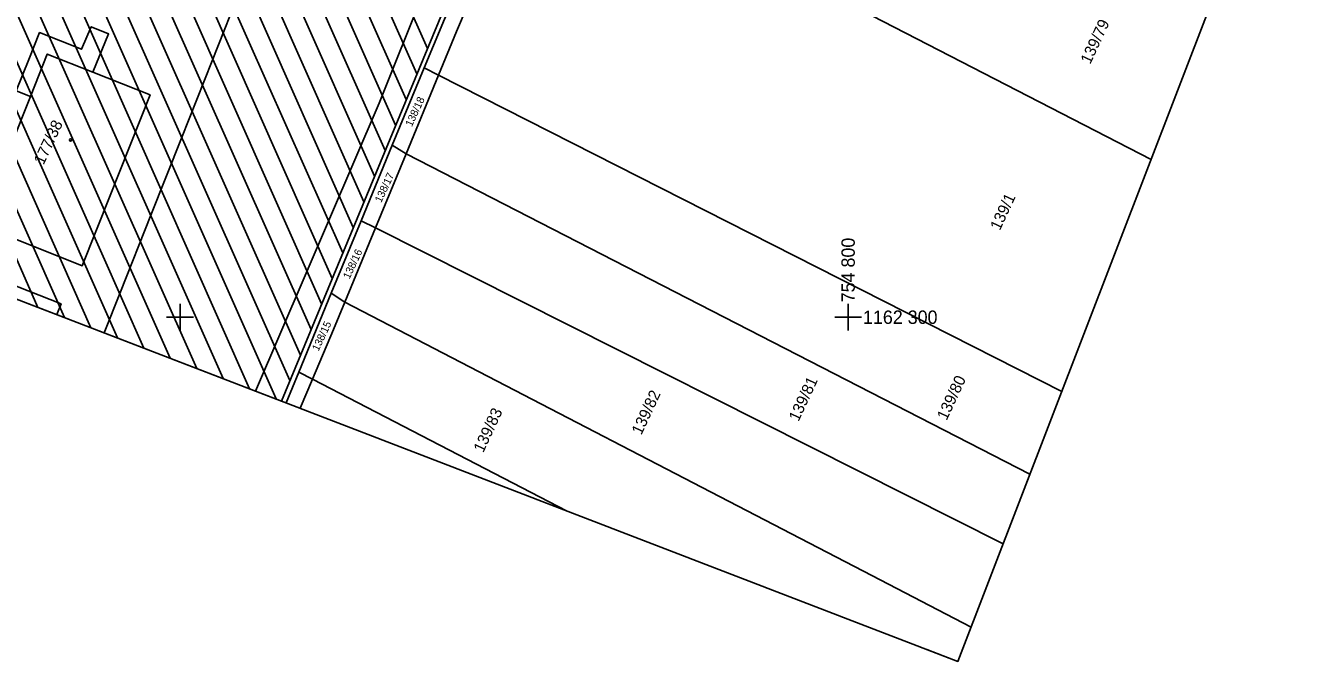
# Model space of a CAD drawing. Extents: x -755061 to -754557, y -1162352 to -1161657.
# Drawn here: x -754923.1 to -754731.6, y -1162351.5 to -1162256.4 of the extents above; entities that cross this region are included whole.
import ezdxf

# ---------------------------------------------------------------- set-up
doc = ezdxf.new("R2010")
doc.units = 0
for name, color, linetype in [('ADJ_Formát', 7, 'Continuous'), ('ADJ_Síť', 7, 'Continuous'), ('DTA_správa_investora', 7, 'Continuous'), ('KN_Katastrální hranice', 7, 'Continuous'), ('KN_Vrstva 55', 7, 'Continuous'), ('KN_Vrstva 56', 7, 'Continuous'), ('KN_Vrstva 57', 7, 'Continuous'), ('KN_Vrstva 59', 7, 'Continuous'), ('Vrstva 53', 7, 'Continuous')]:
    doc.layers.add(name, color=color, linetype=linetype)

msp = doc.modelspace()

# ---------------------------------------------------------------- linework, layer by layer
at = {"layer": 'ADJ_Formát'}
msp.add_line((-754783.57, -1162351.52), (-754788.23, -1162349.72), dxfattribs=at)
msp.add_lwpolyline([(-754909.9, -1161852.87), (-754632.71, -1161959.54), (-754783.57, -1162351.52), (-755060.75, -1162244.84)], close=True, dxfattribs=at)
at = {"layer": 'ADJ_Síť'}
for points in [[(-754900, -1162298), (-754900, -1162300), (-754900, -1162302)], [(-754900, -1162298), (-754900, -1162300), (-754900, -1162302)], [(-754800, -1162298), (-754800, -1162300), (-754800, -1162302)], [(-754800, -1162298), (-754800, -1162300), (-754800, -1162302)], [(-754898, -1162300), (-754900, -1162300), (-754902, -1162300)], [(-754898, -1162300), (-754900, -1162300), (-754902, -1162300)], [(-754798, -1162300), (-754800, -1162300), (-754802, -1162300)], [(-754798, -1162300), (-754800, -1162300), (-754802, -1162300)]]:
    msp.add_lwpolyline(points, dxfattribs=at)
at = {"layer": 'DTA_správa_investora'}
for p, q in [((-754862.97, -1162259.78), (-754899.89, -1162176.65)), ((-754866.14, -1162267.42), (-754904.89, -1162180.18)), ((-754864.55, -1162263.6), (-754902.39, -1162178.42)), ((-754867.72, -1162271.25), (-754907.39, -1162181.94)), ((-754869.3, -1162275.07), (-754909.89, -1162183.71)), ((-754870.89, -1162278.9), (-754912.39, -1162185.47)), ((-754872.47, -1162282.72), (-754914.89, -1162187.24)), ((-754874.06, -1162286.55), (-754917.47, -1162188.82)), ((-754875.64, -1162290.37), (-754920.09, -1162190.29)), ((-754878.81, -1162298.02), (-754925.34, -1162193.26)), ((-754877.22, -1162294.2), (-754922.72, -1162191.76)), ((-754880.39, -1162301.85), (-754927.96, -1162194.76)), ((-754881.97, -1162305.67), (-754930.57, -1162196.26)), ((-754885.62, -1162312.24), (-754935.81, -1162199.26)), ((-754883.56, -1162309.49), (-754933.19, -1162197.76)), ((-754889.58, -1162310.72), (-754938.42, -1162200.76)), ((-754893.54, -1162309.19), (-754941.04, -1162202.26)), ((-754901.46, -1162306.15), (-754946.44, -1162204.88)), ((-754897.5, -1162307.67), (-754943.74, -1162203.57)), ((-754905.42, -1162304.62), (-754949.14, -1162206.19)), ((-754913.34, -1162301.58), (-754954.55, -1162208.8)), ((-754909.38, -1162303.1), (-754951.85, -1162207.49)), ((-754917.3, -1162300.05), (-754957.25, -1162210.1)), ((-754921.26, -1162298.53), (-754959.95, -1162211.41))]:
    msp.add_line(p, q, dxfattribs=at)
msp.add_lwpolyline([(-755057.07, -1162235.3), (-755060.75, -1162244.84), (-754884.82, -1162312.55), (-754851.45, -1162231.96), (-754816.22, -1162147.35), (-754802.96, -1162113.9), (-754798.15, -1162101.07), (-754793.13, -1162087.4), (-754789, -1162076.26), (-754760.29, -1162004.33), (-754756.33, -1161996.85), (-754754.27, -1161988.55), (-754747.84, -1161978.77), (-754745.89, -1161978.47), (-754750.32, -1161972.64), (-754749.74, -1161970.12), (-754747.41, -1161959.83), (-754731.42, -1161979.09), (-754717.5, -1161955.11), (-754704.12, -1161932.06), (-754747.69, -1161915.3)], dxfattribs=at)
at = {"layer": 'KN_Katastrální hranice'}
msp.add_lwpolyline([(-754816.22, -1162147.35), (-754851.45, -1162231.96), (-754884.82, -1162312.55)], dxfattribs=at)
at = {"layer": 'KN_Vrstva 55'}
for p, q in [((-754863.44, -1162262.66), (-754848.96, -1162227.81)), ((-754868.25, -1162274.25), (-754863.44, -1162262.66)), ((-754861.29, -1162263.76), (-754866.17, -1162275.57)), ((-754861.29, -1162263.76), (-754863.44, -1162262.66)), ((-754872.9, -1162285.56), (-754868.25, -1162274.25)), ((-754866.17, -1162275.57), (-754870.74, -1162286.62)), ((-754866.17, -1162275.57), (-754868.25, -1162274.25)), ((-754877.36, -1162296.41), (-754872.9, -1162285.56)), ((-754870.74, -1162286.62), (-754872.9, -1162285.56)), ((-754870.74, -1162286.62), (-754875.34, -1162297.75)), ((-754882.21, -1162308.21), (-754877.36, -1162296.41)), ((-754875.34, -1162297.75), (-754877.36, -1162296.41)), ((-754884.11, -1162312.82), (-754882.21, -1162308.21)), ((-754880.18, -1162309.28), (-754882.21, -1162308.21)), ((-754880.18, -1162309.28), (-754882.02, -1162313.63)), ((-754880.18, -1162309.28), (-754842.03, -1162329.02))]:
    msp.add_line(p, q, dxfattribs=at)
for points in [[(-754888.68, -1162311.07), (-754870.17, -1162267.96), (-754836.4, -1162183.6), (-754824.89, -1162157.4), (-754808.97, -1162117.64), (-754790.52, -1162068.93), (-754761.32, -1161999.17), (-754754.27, -1161988.55)], [(-754816.22, -1162147.35), (-754851.45, -1162231.96), (-754884.82, -1162312.55)], [(-754816.22, -1162147.35), (-754851.45, -1162231.96), (-754884.82, -1162312.55)], [(-754878.41, -1162219.27), (-754890.63, -1162250.1), (-754895.21, -1162261.65), (-754899.8, -1162273.21), (-754904.37, -1162284.73), (-754908.92, -1162296.21), (-754911.35, -1162302.34)], [(-754846.58, -1162228.99), (-754858.59, -1162257.23), (-754861.29, -1162263.76)], [(-754754.65, -1162276.39), (-754846.58, -1162228.99)], [(-754922.63, -1162261.43), (-754921.01, -1162257.39), (-754914.72, -1162259.89), (-754913.29, -1162256.54), (-754910.69, -1162257.6), (-754913.05, -1162263.33), (-754904.47, -1162266.73), (-754905.81, -1162270.11), (-754910.45, -1162281.8), (-754914.62, -1162292.29), (-754930, -1162286.19), (-754925.41, -1162274.6), (-754922.38, -1162266.96), (-754924.5, -1162266.11), (-754922.63, -1162261.43)], [(-754861.29, -1162263.76), (-754768.03, -1162311.14)], [(-754866.17, -1162275.57), (-754772.78, -1162323.49)], [(-754870.74, -1162286.62), (-754776.8, -1162333.94)], [(-754930.78, -1162292.9), (-754917.8, -1162298.01), (-754918.43, -1162299.61)], [(-754875.34, -1162297.75), (-754877.03, -1162301.83), (-754880.18, -1162309.28)], [(-754875.34, -1162297.75), (-754796.43, -1162338.66), (-754781.59, -1162346.38)]]:
    msp.add_lwpolyline(points, dxfattribs=at)
at = {"layer": 'KN_Vrstva 56'}
msp.add_lwpolyline([(-754922.38, -1162266.96), (-754919.87, -1162260.62), (-754913.05, -1162263.33)], dxfattribs=at)
at = {"layer": 'KN_Vrstva 59'}
msp.add_circle((-754916.37, -1162273.47), 0.175, dxfattribs=at)
at = {"layer": 'Vrstva 53'}
msp.add_lwpolyline([(-754884.82, -1162312.55), (-754851.45, -1162231.96), (-754816.22, -1162147.35), (-754802.96, -1162113.9), (-754798.15, -1162101.07), (-754793.13, -1162087.4), (-754789, -1162076.26), (-754760.29, -1162004.33), (-754756.33, -1161996.85), (-754754.27, -1161988.55), (-754747.84, -1161978.77), (-754745.89, -1161978.47), (-754750.32, -1161972.64), (-754749.74, -1161970.12), (-754747.41, -1161959.83), (-754731.42, -1161979.09), (-754717.5, -1161955.11), (-754704.12, -1161932.06)], dxfattribs=at)

# ---------------------------------------------------------------- texts
at = {"layer": 'ADJ_Síť'}
msp.add_text('   754 800', height=2, rotation=90, dxfattribs=at).set_placement((-754799, -1162300))
msp.add_text('   1162 300', height=2, dxfattribs=at).set_placement((-754800, -1162301))
at = {"layer": 'KN_Vrstva 57'}
for s, height, p in [('139/79', 1.7, (-754763.76, -1162262.23)), ('138/18', 1.139, (-754865.3, -1162271.57)), ('177/38', 1.7, (-754920.43, -1162277.31)), ('138/17', 1.139, (-754869.88, -1162282.94)), ('139/1', 1.7, (-754777.29, -1162287.13)), ('138/16', 1.139, (-754874.63, -1162294.37)), ('138/15', 1.139, (-754879.27, -1162305.16)), ('139/81', 1.7, (-754807.43, -1162315.72)), ('139/80', 1.7, (-754785.25, -1162315.54)), ('139/82', 1.7, (-754830.95, -1162317.73)), ('139/83', 1.7, (-754854.62, -1162320.39))]:
    msp.add_text(s, height=height, rotation=65, dxfattribs=at).set_placement(p)

doc.saveas('drawing.dxf')
